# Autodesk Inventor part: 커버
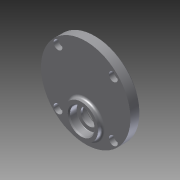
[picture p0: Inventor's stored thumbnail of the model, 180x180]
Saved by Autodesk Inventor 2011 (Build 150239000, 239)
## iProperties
Created: 2014-12
Part Number: 커버
Document SubType Name: Modeling
Designer: Administrator
Density: 1 g/cm^3
Author: Administrator
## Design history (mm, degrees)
sketch "스케치1"
  geometry: C1 r 40 at (0, 0); 1 further point
  constraints: 1 centre point, 1 coincident
  dimensions: "d0" = 80 diameter of C1
extrude "돌출1" new body sketch "스케치1" distance "d1" = 9; taper "d2" = 0 deg
sketch "스케치2"
  geometry: C1 r 40 at (0, 0) reference; C2 r 15 at (0, -20)
  constraints: 1 centre point, 1 vertical alignment
  dimensions: "d3" = 30 diameter of C2; "d4" = 20 distance of C1.centre C2.centre
extrude "돌출2" join sketch "스케치2" distance "d5" = 4; taper "d6" = 0 deg
sketch "스케치3"
  geometry: C1 r 40 at (0, 0) reference; C2 r 14 at (0, -11); C3 r 14 at (0, 20)
  constraints: 2 centre point, 2 vertical alignment
  dimensions: "d7" = 28 diameter of C2; "d8" = 28 diameter of C3; "d9" = 11 distance of C2.centre C1.centre; "d10" = 20 distance of C3.centre C1.centre
extrude "돌출3" join sketch "스케치3" distance "d11" = 3; taper "d12" = 0 deg
hole "Hole1" diameter "d15" = 22; stored, may be unused: countersink angle "d19" = 90 deg, drill point angle "d21" = 0 deg; dims "d13" = 10, "d14" = 10, "d16" = 6, "d17" = 4, "d18" = 2, "d20" = 7
hole "Hole2" diameter "d24" = 18; stored, may be unused: countersink angle "d28" = 90 deg, drill point angle "d30" = 0 deg; dims "d22" = 10, "d23" = 10, "d25" = 6, "d26" = 4, "d27" = 2, "d29" = 1
hole "Hole3" diameter "d33" = 22; stored, may be unused: countersink angle "d37" = 90 deg, drill point angle "d39" = 0 deg; dims "d31" = 10, "d32" = 10, "d34" = 6, "d35" = 4, "d36" = 2, "d38" = 7
hole "Hole4" diameter "d42" = 15; stored, may be unused: countersink angle "d46" = 90 deg, drill point angle "d48" = 0 deg; dims "d40" = 10, "d41" = 10, "d43" = 6, "d44" = 4, "d45" = 2, "d47" = 2
hole "Hole5" diameter "d51" = 22; stored, may be unused: countersink angle "d55" = 90 deg, drill point angle "d57" = 0 deg; dims "d49" = 10, "d50" = 10, "d52" = 6, "d53" = 4, "d54" = 2, "d56" = 7
sketch "스케치4" dims "d58" = 70
  geometry: L1 (0, 0)-(24.749, 24.749); L2 (0, 0)-(35, 0); C1 r 40 at (0, 0) reference; 1 further point
  constraints: 4 end point, 2 coincident, 1 equal length, 1 horizontal, 3 other
  dimensions: "d59" = 45 deg angle of L2 L1
hole "Hole6" sketch "스케치4" at (24.749, 24.749) diameter "d60" = 4.5; stored, may be unused: countersink angle "d64" = 90 deg, drill point angle "d66" = 0 deg; dims "d61" = 6, "d62" = 8, "d63" = 4.4, "d65" = 7
chamfer "모따기1" distance "d70" = 1; stored, may be unused: second distance "d71" = 2, angle "d72" = 45 deg
fillet "모깎기1" dims "d73" = 2, "d74" = 0.3
node "솔리드1"
pattern_circular "원형 패턴1" dims angle "d68" = 360 deg
